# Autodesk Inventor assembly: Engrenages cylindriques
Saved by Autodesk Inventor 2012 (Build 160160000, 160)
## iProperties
Created: 2011-10
Part Number: Engrenages cylindriques
Document SubType Name: Assembly
Designer: Laur
ClientObjectVersion: 1
Author: Laur
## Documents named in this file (2)
- D:\Formulaire\Sujet CIM 2012\Modélisation_7970_shimano\arbre moteur et pignon 11 dents m0,25\Design Accelerator\Engrenages cylindriques1.iam
- D:\Formulaire\Sujet CIM 2012\Modélisation_7970_shimano\arbre moteur et pignon 11 dents m0,25\Design Accelerator\Engrenage cylindrique11.ipt
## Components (1 placed, 1 different names)
1. Engrenage cylindrique1:1
